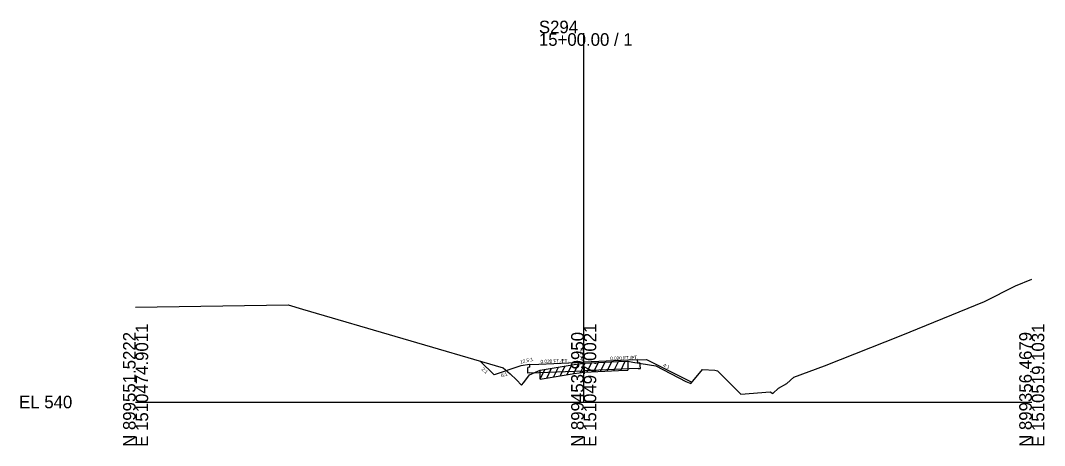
# Model space of a CAD drawing. Extents: x 974 to 2203, y -10 to 19041.
# Drawn here: x 974.3 to 1202.8, y 9990.3 to 10085 of the extents above; entities that cross this region are included whole.
import ezdxf

# ---------------------------------------------------------------- set-up
doc = ezdxf.new("R2010")
doc.units = 0
for name, color, linetype in [('RD_GPK_XS_Cell', 7, 'Continuous'), ('RD_XS_Base', 7, 'Continuous'), ('RD_XS_EarthShd', 7, 'Continuous'), ('RD_XS_ExGround', 7, 'Continuous'), ('RD_XS_ExPaveRet', 7, 'Continuous'), ('RD_XS_Pave', 7, 'Continuous'), ('RD_XS_TX_Elev_EX', 7, 'Continuous'), ('RD_XS_TX_Slope', 7, 'Continuous')]:
    doc.layers.add(name, color=color, linetype=linetype)

msp = doc.modelspace()

# ---------------------------------------------------------------- linework, layer by layer
at = {"layer": 'RD_GPK_XS_Cell'}
for p, q in [((1100, 10000), (1100, 10082.19)), ((1000, 10000), (1100, 10000)), ((1100, 10000), (1200, 10000))]:
    msp.add_line(p, q, dxfattribs=at)
at = {"layer": 'RD_XS_Base'}
for p, q in [((1088, 10007.74), (1087.5, 10007.72)), ((1087.5, 10006.45), (1087.5, 10007.72)), ((1088, 10007.74), (1088, 10008.38)), ((1112.16, 10007.48), (1110.16, 10007.4)), ((1112.05, 10008.75), (1112, 10009.38)), ((1112.05, 10008.75), (1112.55, 10008.77)), ((1112.16, 10007.48), (1112.66, 10007.5)), ((1112.66, 10007.5), (1112.55, 10008.77)), ((1088, 10006.47), (1087.5, 10006.45)), ((1088, 10006.47), (1090, 10006.56)), ((1090, 10006.56), (1099.99, 10006.97)), ((1110.16, 10007.4), (1099.99, 10006.97))]:
    msp.add_line(p, q, dxfattribs=at)
at = {"layer": 'RD_XS_EarthShd'}
for p, q in [((1080, 10006.05), (1076.93, 10009.12)), ((1086, 10008.05), (1080, 10006.05)), ((1088, 10008.38), (1086, 10008.05)), ((1112, 10009.38), (1114, 10009.46)), ((1114, 10009.46), (1124.15, 10004.39))]:
    msp.add_line(p, q, dxfattribs=at)
at = {"layer": 'RD_XS_ExGround'}
msp.add_lwpolyline([(1000, 10021.12), (1034.04, 10021.64), (1037.24, 10020.67), (1081.99, 10007.65), (1083.58, 10006.3), (1084.99, 10004.93), (1086.13, 10003.73), (1086.61, 10004.34), (1087.94, 10006.04), (1089.73, 10006.84), (1090.25, 10007.09), (1097.89, 10008.33), (1100.1, 10008.67), (1107.73, 10009.02), (1109.83, 10009.09), (1110.95, 10008.88), (1116.09, 10008.05), (1122.8, 10004.6), (1123.92, 10004.11), (1126.19, 10006.87), (1126.51, 10007.24), (1129.24, 10007.08), (1129.86, 10006.95), (1135.06, 10001.78), (1141.61, 10002.23), (1142.2, 10001.86), (1143.47, 10003.09), (1145.33, 10004.15), (1146.92, 10005.5), (1153.76, 10008.06), (1170.84, 10014.79), (1189.45, 10022.41), (1196.4, 10025.92), (1200, 10027.4)], dxfattribs=at)
at = {"layer": 'RD_XS_ExPaveRet'}
for p, q in [((1091.75, 10005.33), (1092.84, 10007.51)), ((1093.25, 10005.57), (1094.34, 10007.75)), ((1094.75, 10005.82), (1095.84, 10008)), ((1096.25, 10006.06), (1097.34, 10008.24)), ((1097.75, 10006.31), (1098.83, 10008.47)), ((1099.25, 10006.54), (1100.32, 10008.68)), ((1100.75, 10006.7), (1101.77, 10008.74)), ((1102.25, 10006.77), (1103.27, 10008.81)), ((1103.75, 10006.84), (1104.77, 10008.88)), ((1105.25, 10006.91), (1106.27, 10008.95)), ((1106.75, 10006.98), (1107.77, 10009.02)), ((1108.25, 10007.04), (1109.27, 10009.07)), ((1109.83, 10009.09), (1109.83, 10007.09)), ((1090.25, 10005.09), (1091.34, 10007.26)), ((1090.25, 10005.09), (1090.25, 10007.09)), ((1090.25, 10005.09), (1097.89, 10006.33)), ((1097.89, 10006.33), (1100.1, 10006.67)), ((1100.1, 10006.67), (1107.73, 10007.02)), ((1107.73, 10007.02), (1109.83, 10007.09))]:
    msp.add_line(p, q, dxfattribs=at)
at = {"layer": 'RD_XS_Pave'}
for p, q in [((1088, 10008.38), (1090, 10008.46)), ((1090, 10008.46), (1100, 10008.88)), ((1110, 10009.3), (1100, 10008.88)), ((1112, 10009.38), (1110, 10009.3))]:
    msp.add_line(p, q, dxfattribs=at)

# ---------------------------------------------------------------- texts
at = {"layer": 'RD_GPK_XS_Cell'}
for s, p in [('S294', (1090, 10082.19)), ('15+00.00 / 1', (1090, 10079.39)), ('EL 540', (974, 9998.6))]:
    msp.add_text(s, height=2.8, dxfattribs=at).set_placement(p)
for s, p in [('E 1510474.9011', (1002.8, 9990)), ('E 1510497.0021', (1102.8, 9990)), ('E 1510519.1031', (1202.8, 9990)), ('N 899551.5222', (1000, 9990)), ('N 899453.9950', (1100, 9990)), ('N 899356.4679', (1200, 9990))]:
    msp.add_text(s, height=2.8, rotation=90, dxfattribs=at).set_placement(p)
at = {"layer": 'RD_XS_TX_Elev_EX'}
msp.add_text('544.33', height=0.75, rotation=90, dxfattribs=at).set_placement((1100, 10008.56))
at = {"layer": 'RD_XS_TX_Slope'}
for s, height, rotation, p in [('12.5:1', 0.778, 12.7511, (1085.88, 10008.51)), ('0.020 FT./FT.', 0.7518, 2.1396, (1105.93, 10009.34)), ('2:1', 0.778, 319.3411, (1077.1, 10007.19)), ('0.020 FT./FT.', 0.7518, 1.8449, (1090.38, 10008.64)), ('4:1', 0.778, 333.6312, (1117.62, 10007.97)), ('6:1', 0.778, 19.3982, (1081.66, 10005.48))]:
    msp.add_text(s, height=height, rotation=rotation, dxfattribs=at).set_placement(p)

doc.saveas('drawing.dxf')
